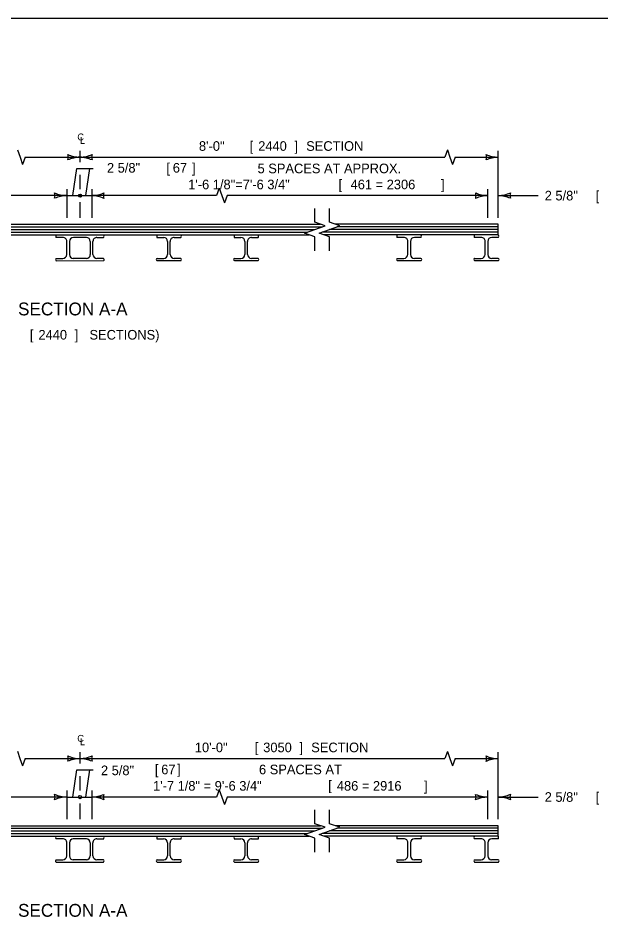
# Model space of a CAD drawing. Extents: x 49991.4 to 50021, y 49987.6 to 50011.4.
# Drawn here: x 50002.38 to 50006.02, y 49993.35 to 49999 of the extents above; entities that cross this region are included whole.
import ezdxf

# ---------------------------------------------------------------- set-up
doc = ezdxf.new("R2010")
doc.units = 0
for name, color, linetype in [('Level 1', 7, 'Continuous'), ('Level 10', 7, 'Continuous'), ('Level 2', 7, 'Continuous'), ('Level 3', 7, 'Continuous'), ('Level 6', 7, 'Continuous')]:
    doc.layers.add(name, color=color, linetype=linetype)

msp = doc.modelspace()

# ---------------------------------------------------------------- linework, layer by layer
at = {"layer": 'Level 1'}
for p, q in [((50001.3411, 49997.7121), (50004.2726, 49997.7121)), ((50005.3818, 49997.7121), (50004.3638, 49997.7121)), ((50005.3818, 49997.6465), (50005.3818, 49997.7121)), ((50001.2596, 49997.663), (50004.1911, 49997.663)), ((50001.2701, 49997.6465), (50004.2016, 49997.6465)), ((50001.3056, 49997.6793), (50004.2371, 49997.6793)), ((50001.3518, 49997.6957), (50004.2833, 49997.6957)), ((50002.6221, 49997.6461), (50002.918, 49997.6462)), ((50003.2526, 49997.646), (50003.4005, 49997.6462)), ((50003.7352, 49997.646), (50003.8832, 49997.6462)), ((50005.3818, 49997.663), (50004.2823, 49997.663)), ((50005.3818, 49997.6465), (50004.2928, 49997.6465)), ((50005.3818, 49997.6793), (50004.3283, 49997.6793)), ((50005.3818, 49997.6957), (50004.3745, 49997.6957)), ((50004.8992, 49997.6461), (50004.7513, 49997.6463)), ((50005.3818, 49997.6461), (50005.2339, 49997.6463)), ((50002.6637, 49997.6297), (50002.6222, 49997.6297)), ((50002.6881, 49997.5237), (50002.6881, 49997.6052)), ((50002.7048, 49997.6051), (50002.7048, 49997.5235)), ((50002.8107, 49997.6297), (50002.7294, 49997.6295)), ((50002.8353, 49997.6052), (50002.8353, 49997.5236)), ((50002.852, 49997.5239), (50002.852, 49997.6053)), ((50002.8763, 49997.6298), (50002.918, 49997.6299)), ((50003.2527, 49997.6296), (50003.2933, 49997.6297)), ((50003.3178, 49997.6052), (50003.3178, 49997.5236)), ((50003.3346, 49997.5239), (50003.3346, 49997.6053)), ((50003.3589, 49997.6298), (50003.4005, 49997.6299)), ((50003.7353, 49997.6296), (50003.7759, 49997.6297)), ((50003.8004, 49997.6052), (50003.8004, 49997.5236)), ((50003.8172, 49997.5239), (50003.8172, 49997.6053)), ((50003.8415, 49997.6298), (50003.8832, 49997.6299)), ((50004.7929, 49997.6299), (50004.7513, 49997.6299)), ((50004.8172, 49997.5239), (50004.8172, 49997.6054)), ((50004.834, 49997.6053), (50004.834, 49997.5237)), ((50004.8992, 49997.6297), (50004.8586, 49997.6298)), ((50005.2755, 49997.6299), (50005.2339, 49997.6299)), ((50005.2998, 49997.5239), (50005.2998, 49997.6054)), ((50005.3166, 49997.6053), (50005.3166, 49997.5237)), ((50005.3818, 49997.6297), (50005.3412, 49997.6298)), ((50002.6213, 49997.4851), (50002.9185, 49997.4852)), ((50002.6221, 49997.4993), (50002.6635, 49997.4993)), ((50002.8108, 49997.4991), (50002.7293, 49997.4989)), ((50002.918, 49997.4994), (50002.8766, 49997.4994)), ((50003.2523, 49997.4852), (50003.4011, 49997.4852)), ((50003.253, 49997.499), (50003.2934, 49997.4991)), ((50003.4006, 49997.4994), (50003.3592, 49997.4994)), ((50003.7348, 49997.4852), (50003.8838, 49997.4852)), ((50003.7356, 49997.499), (50003.776, 49997.4991)), ((50003.8832, 49997.4994), (50003.8418, 49997.4994)), ((50004.7506, 49997.4853), (50004.8999, 49997.4853)), ((50004.7513, 49997.4995), (50004.7927, 49997.4995)), ((50004.8989, 49997.4991), (50004.8584, 49997.4991)), ((50005.233, 49997.4854), (50005.3828, 49997.4854)), ((50005.2339, 49997.4995), (50005.2753, 49997.4995)), ((50005.3815, 49997.4991), (50005.341, 49997.4991)), ((50001.3055, 49993.9253), (50004.237, 49993.9253)), ((50001.341, 49993.9581), (50004.2725, 49993.9581)), ((50001.3517, 49993.9417), (50004.2832, 49993.9417)), ((50005.3817, 49993.9253), (50004.3282, 49993.9253)), ((50005.3817, 49993.9581), (50004.3637, 49993.9581)), ((50005.3817, 49993.9417), (50004.3744, 49993.9417)), ((50005.3817, 49993.8925), (50005.3817, 49993.9581)), ((50001.2595, 49993.909), (50004.191, 49993.909)), ((50001.27, 49993.8925), (50004.2015, 49993.8925)), ((50002.6221, 49993.8921), (50002.9178, 49993.8922)), ((50002.6636, 49993.8757), (50002.6221, 49993.8757)), ((50002.8106, 49993.8757), (50002.7293, 49993.8755)), ((50002.8762, 49993.8758), (50002.9178, 49993.8759)), ((50003.2525, 49993.892), (50003.4005, 49993.8922)), ((50003.2526, 49993.8756), (50003.2932, 49993.8757)), ((50003.3588, 49993.8758), (50003.4005, 49993.8759)), ((50003.7351, 49993.892), (50003.8831, 49993.8922)), ((50003.7352, 49993.8756), (50003.7758, 49993.8757)), ((50003.8414, 49993.8758), (50003.8831, 49993.8759)), ((50005.3817, 49993.909), (50004.2822, 49993.909)), ((50005.3817, 49993.8925), (50004.2927, 49993.8925)), ((50004.8991, 49993.8921), (50004.7512, 49993.8923)), ((50004.7928, 49993.8759), (50004.7512, 49993.8759)), ((50004.8991, 49993.8757), (50004.8585, 49993.8758)), ((50005.3817, 49993.8921), (50005.2338, 49993.8923)), ((50005.2754, 49993.8759), (50005.2338, 49993.8759)), ((50005.3817, 49993.8757), (50005.3411, 49993.8758)), ((50002.688, 49993.7697), (50002.688, 49993.8512)), ((50002.7047, 49993.8511), (50002.7047, 49993.7695)), ((50002.8352, 49993.8512), (50002.8352, 49993.7696)), ((50002.8519, 49993.7699), (50002.8519, 49993.8513)), ((50003.3177, 49993.8512), (50003.3177, 49993.7696)), ((50003.3345, 49993.7699), (50003.3345, 49993.8513)), ((50003.8003, 49993.8512), (50003.8003, 49993.7696)), ((50003.8171, 49993.7699), (50003.8171, 49993.8513)), ((50004.8171, 49993.7699), (50004.8171, 49993.8514)), ((50004.8339, 49993.8513), (50004.8339, 49993.7697)), ((50005.2997, 49993.7699), (50005.2997, 49993.8514)), ((50005.3165, 49993.8513), (50005.3165, 49993.7697)), ((50002.622, 49993.7453), (50002.6634, 49993.7453)), ((50002.8107, 49993.7451), (50002.7292, 49993.7449)), ((50002.9179, 49993.7454), (50002.8765, 49993.7454)), ((50003.2529, 49993.745), (50003.2933, 49993.7451)), ((50003.4005, 49993.7454), (50003.3591, 49993.7454)), ((50003.7355, 49993.745), (50003.7759, 49993.7451)), ((50003.8831, 49993.7454), (50003.8417, 49993.7454)), ((50004.7512, 49993.7455), (50004.7926, 49993.7455)), ((50004.8988, 49993.7451), (50004.8583, 49993.7451)), ((50005.2338, 49993.7455), (50005.2752, 49993.7455)), ((50005.3814, 49993.7451), (50005.3409, 49993.7451)), ((50002.6212, 49993.7311), (50002.9184, 49993.7312)), ((50003.2522, 49993.7312), (50003.401, 49993.7312)), ((50003.7347, 49993.7312), (50003.8837, 49993.7312)), ((50004.7505, 49993.7313), (50004.8998, 49993.7313)), ((50005.2329, 49993.7314), (50005.3827, 49993.7314))]:
    msp.add_line(p, q, dxfattribs=at)
msp.add_lwpolyline([(49999.3835, 49998.9992), (50016.7501, 49998.9992), (50016.7501, 49987.7988), (49999.3835, 49987.7988)], close=True, dxfattribs=at)
for centre, radius, start, end in [((50002.6644, 49997.606), 0.0237, 358.1433, 91.4997), ((50002.7293, 49997.605), 0.0245, 89.8692, 179.8692), ((50002.8108, 49997.6052), 0.0245, 0.1309, 90.1308), ((50002.8756, 49997.6062), 0.0237, 88.3061, 182.0509), ((50003.2933, 49997.6052), 0.0245, 0.1309, 90.1308), ((50003.3572, 49997.6072), 0.0227, 85.6929, 184.6641), ((50003.7759, 49997.6052), 0.0245, 0.1309, 90.1308), ((50003.8406, 49997.6064), 0.0234, 87.6491, 182.7079), ((50004.7943, 49997.6069), 0.023, 356.1633, 93.4797), ((50004.8585, 49997.6053), 0.0245, 89.8692, 179.8692), ((50005.2766, 49997.6066), 0.0233, 356.9743, 92.6686), ((50005.3411, 49997.6053), 0.0245, 89.8692, 179.8692), ((50002.6636, 49997.5238), 0.0245, 269.8691, 359.8691), ((50002.7293, 49997.5234), 0.0245, 179.8691, 269.8691), ((50002.8108, 49997.5236), 0.0245, 270.1309, 0.1308), ((50002.8765, 49997.5239), 0.0245, 180.1309, 270.1309), ((50003.2933, 49997.5236), 0.0245, 270.1309, 0.1308), ((50003.3591, 49997.5239), 0.0245, 180.1309, 270.1309), ((50003.7759, 49997.5236), 0.0245, 270.1309, 0.1308), ((50003.8417, 49997.5239), 0.0245, 180.1309, 270.1309), ((50004.7927, 49997.524), 0.0245, 269.8691, 359.8691), ((50004.8585, 49997.5236), 0.0245, 179.8691, 269.8691), ((50005.2753, 49997.524), 0.0245, 269.8691, 359.8691), ((50005.3411, 49997.5236), 0.0245, 179.8691, 269.8691), ((50002.6661, 49993.8538), 0.022, 353.1725, 96.4705), ((50002.7292, 49993.851), 0.0245, 89.8692, 179.8692), ((50002.8107, 49993.8512), 0.0245, 0.1309, 90.1308), ((50002.8745, 49993.8532), 0.0227, 85.5502, 184.8068), ((50003.2932, 49993.8512), 0.0245, 0.1309, 90.1308), ((50003.3571, 49993.8533), 0.0226, 85.4784, 184.8786), ((50003.7758, 49993.8512), 0.0245, 0.1309, 90.1308), ((50003.8409, 49993.852), 0.0238, 88.6781, 181.6789), ((50004.7953, 49993.8541), 0.022, 353.0206, 96.6224), ((50004.8584, 49993.8513), 0.0245, 89.8692, 179.8692), ((50005.2765, 49993.8527), 0.0233, 356.9044, 92.7386), ((50005.341, 49993.8513), 0.0245, 89.8692, 179.8692), ((50002.6635, 49993.7698), 0.0245, 269.8691, 359.8691), ((50002.7292, 49993.7694), 0.0245, 179.8691, 269.8691), ((50002.8107, 49993.7696), 0.0245, 270.1309, 0.1308), ((50002.8764, 49993.7699), 0.0245, 180.1309, 270.1309), ((50003.2932, 49993.7696), 0.0245, 270.1309, 0.1308), ((50003.359, 49993.7699), 0.0245, 180.1309, 270.1309), ((50003.7758, 49993.7696), 0.0245, 270.1309, 0.1308), ((50003.8416, 49993.7699), 0.0245, 180.1309, 270.1309), ((50004.7926, 49993.77), 0.0245, 269.8691, 359.8691), ((50004.8584, 49993.7696), 0.0245, 179.8691, 269.8691), ((50005.2752, 49993.77), 0.0245, 269.8691, 359.8691), ((50005.341, 49993.7696), 0.0245, 179.8691, 269.8691)]:
    msp.add_arc(centre, radius, start, end, dxfattribs=at)
for centre, major_axis, ratio, start_param, end_param in [((50002.6221, 49997.6379), (-0.00002, 0.00817), 0.356754, 0, 3.141593), ((50002.9179, 49997.638), (0.00002, -0.00817), 0.392805, 0, 3.141593), ((50003.2527, 49997.6378), (-0.00002, 0.00817), 0.356754, 0, 3.141593), ((50003.4005, 49997.638), (0.00002, -0.00817), 0.392805, 0, 3.141593), ((50003.7353, 49997.6378), (-0.00002, 0.00817), 0.356754, 0, 3.141593), ((50003.8831, 49997.638), (0.00002, -0.00817), 0.392805, 0, 3.141593), ((50004.7513, 49997.6381), (-0.00002, -0.00817), 0.392805, 3.141593, 6.283185), ((50004.8992, 49997.6379), (0.00002, 0.00817), 0.356754, 3.141593, 6.283185), ((50005.2339, 49997.6381), (-0.00002, -0.00817), 0.392805, 3.141593, 6.283185), ((50005.3818, 49997.6379), (0.00002, 0.00817), 0.356754, 3.141593, 6.283185), ((50002.6222, 49997.4921), (0.00003, -0.00717), 0.534325, 3.141593, 6.043934), ((50002.9179, 49997.4922), (-0.00003, -0.00717), 0.534325, 0.146109, 3.141593), ((50003.2532, 49997.492), (-0.00025, 0.00695), 0.928868, 0, 2.951883), ((50003.4005, 49997.4922), (-0.00003, -0.00717), 0.534325, 0.161043, 3.141593), ((50003.7358, 49997.492), (-0.00025, 0.00695), 0.928868, 0, 2.93527), ((50003.8831, 49997.4922), (-0.00003, -0.00717), 0.534325, 0.176923, 3.141593), ((50004.7513, 49997.4923), (0.00003, -0.00717), 0.534325, 3.141593, 6.095489), ((50004.8986, 49997.4921), (0.00025, 0.00695), 0.928868, 3.382741, 6.283185), ((50005.2339, 49997.4923), (0.00003, -0.00717), 0.534325, 3.141593, 6.039934), ((50005.3812, 49997.4921), (0.00025, 0.00695), 0.928868, 3.435164, 6.283185), ((50002.6221, 49993.8839), (-0.00002, -0.00817), 0.392805, 3.141593, 6.283185), ((50002.9178, 49993.884), (0.00002, -0.00817), 0.392805, 0, 3.141593), ((50003.2526, 49993.8838), (-0.00002, 0.00817), 0.356754, 0, 3.141593), ((50003.4004, 49993.884), (0.00002, -0.00817), 0.392805, 0, 3.141593), ((50003.7352, 49993.8838), (-0.00002, 0.00817), 0.356754, 0, 3.141593), ((50003.883, 49993.884), (0.00002, -0.00817), 0.392805, 0, 3.141593), ((50004.7512, 49993.8841), (-0.00002, -0.00817), 0.392805, 3.141593, 6.283185), ((50004.8991, 49993.8839), (0.00002, 0.00817), 0.356754, 3.141593, 6.283185), ((50005.2338, 49993.8841), (-0.00002, -0.00817), 0.392805, 3.141593, 6.283185), ((50005.3817, 49993.8839), (0.00002, 0.00817), 0.356754, 3.141593, 6.283185), ((50002.6221, 49993.7381), (0.00003, -0.00717), 0.534325, 3.141593, 6.043934), ((50002.9178, 49993.7382), (-0.00003, -0.00717), 0.534325, 0.146109, 3.141593), ((50003.2531, 49993.738), (-0.00025, 0.00695), 0.928868, 0, 2.951883), ((50003.4004, 49993.7382), (-0.00003, -0.00717), 0.534325, 0.161043, 3.141593), ((50003.7357, 49993.738), (-0.00025, 0.00695), 0.928868, 0, 2.93527), ((50003.883, 49993.7382), (-0.00003, -0.00717), 0.534325, 0.176923, 3.141593), ((50004.7512, 49993.7383), (0.00003, -0.00717), 0.534325, 3.141593, 6.095489), ((50004.8985, 49993.7381), (0.00025, 0.00695), 0.928868, 3.382741, 6.283185), ((50005.2338, 49993.7383), (0.00003, -0.00717), 0.534325, 3.141593, 6.039934), ((50005.3811, 49993.7381), (0.00025, 0.00695), 0.928868, 3.435164, 6.283185)]:
    msp.add_ellipse(centre, major_axis=major_axis, ratio=ratio, start_param=start_param, end_param=end_param, dxfattribs=at)
at = {"layer": 'Level 10'}
msp.add_line((50002.7701, 49994.4169), (50002.7701, 49994.4169), dxfattribs=at)
at = {"layer": 'Level 3'}
for p, q in [((50002.3802, 49998.1765), (50002.3964, 49998.1309)), ((50002.7702, 49998.1709), (50002.7702, 49998.1009)), ((50005.0643, 49998.1762), (50005.0481, 49998.1306)), ((50005.0643, 49998.1762), (50005.0805, 49998.1306)), ((50005.3819, 49997.7521), (50005.3819, 49998.1706)), ((50002.3964, 49998.1309), (50002.4126, 49998.0851)), ((50002.4288, 49998.1309), (50002.4126, 49998.0851)), ((50002.4288, 49998.1309), (50002.7702, 49998.1309)), ((50002.7702, 49998.1309), (50004.5789, 49998.1306)), ((50004.5789, 49998.1306), (50005.0481, 49998.1306)), ((50005.0805, 49998.1306), (50005.0967, 49998.0848)), ((50005.1129, 49998.1306), (50005.0967, 49998.0848)), ((50005.1129, 49998.1306), (50005.3819, 49998.1306)), ((50002.7256, 49997.8912), (50002.7506, 49998.0609)), ((50002.7506, 49998.0609), (50002.8534, 49998.0609)), ((50002.807, 49997.891), (50002.832, 49998.0609)), ((50002.7702, 49998.0209), (50002.7702, 49997.931)), ((50002.6886, 49997.9312), (50002.6886, 49997.7521)), ((50002.8442, 49997.9309), (50002.8442, 49997.7521)), ((50003.6403, 49997.9367), (50003.6241, 49997.8909)), ((50003.6403, 49997.9367), (50003.6565, 49997.8909)), ((50005.3171, 49997.7521), (50005.3171, 49997.9309)), ((50002.6886, 49997.8912), (50001.0764, 49997.8912)), ((50002.6886, 49997.8912), (50002.8442, 49997.8909)), ((50003.6241, 49997.8909), (50002.8442, 49997.8909)), ((50003.6565, 49997.8909), (50003.6727, 49997.8453)), ((50003.6889, 49997.8909), (50003.6727, 49997.8453)), ((50005.3171, 49997.8909), (50003.6889, 49997.8909)), ((50005.3819, 49997.8912), (50005.6321, 49997.8912)), ((50002.7702, 49997.851), (50002.7702, 49997.7521)), ((50002.3801, 49994.4225), (50002.3963, 49994.3769)), ((50005.0642, 49994.4222), (50005.048, 49994.3766)), ((50005.0642, 49994.4222), (50005.0804, 49994.3766)), ((50002.3963, 49994.3769), (50002.4125, 49994.3311)), ((50002.4287, 49994.3769), (50002.4125, 49994.3311)), ((50002.4287, 49994.3769), (50002.7701, 49994.3769)), ((50002.7701, 49994.4169), (50002.7701, 49994.3469)), ((50002.7701, 49994.3769), (50004.5788, 49994.3766)), ((50004.5788, 49994.3766), (50005.048, 49994.3766)), ((50005.0804, 49994.3766), (50005.0966, 49994.3308)), ((50005.1128, 49994.3766), (50005.0966, 49994.3308)), ((50005.1128, 49994.3766), (50005.3818, 49994.3766)), ((50005.3818, 49993.9981), (50005.3818, 49994.4166)), ((50002.7255, 49994.1371), (50002.7505, 49994.3069)), ((50002.7505, 49994.3069), (50002.8533, 49994.3069)), ((50002.7701, 49994.2669), (50002.7701, 49994.177)), ((50002.8069, 49994.137), (50002.8319, 49994.3069)), ((50002.6885, 49994.1772), (50002.6885, 49993.9981)), ((50002.8441, 49994.1769), (50002.8441, 49993.9981)), ((50003.6402, 49994.1827), (50003.624, 49994.1369)), ((50003.6402, 49994.1827), (50003.6564, 49994.1369)), ((50005.317, 49993.9981), (50005.317, 49994.1769)), ((50002.6885, 49994.1372), (50001.0763, 49994.1372)), ((50002.6885, 49994.1372), (50002.8441, 49994.1369)), ((50002.7701, 49994.097), (50002.7701, 49993.9981)), ((50003.624, 49994.1369), (50002.8441, 49994.1369)), ((50003.6564, 49994.1369), (50003.6726, 49994.0913)), ((50003.6888, 49994.1369), (50003.6726, 49994.0913)), ((50005.317, 49994.1369), (50003.6888, 49994.1369)), ((50005.3818, 49994.1372), (50005.632, 49994.1372))]:
    msp.add_line(p, q, dxfattribs=at)
for centre in [(50002.771, 49997.8906), (50002.7709, 49994.1366)]:
    msp.add_circle(centre, 0.01, dxfattribs=at)
for centre, radius, start, end in [((50002.7794, 49998.353), 0.2223, 247.456, 267.6395), ((50002.642, 49998.1309), 0.0548, 342.1388, 17.8612), ((50002.7817, 49997.8982), 0.233, 92.8273, 112.0772), ((50002.7588, 49998.3636), 0.233, 272.8273, 292.0772), ((50002.7611, 49997.9088), 0.2223, 67.456, 87.6395), ((50002.8985, 49998.1309), 0.0548, 162.1388, 197.8612), ((50005.3911, 49998.3528), 0.2223, 247.456, 267.6395), ((50005.2537, 49998.1306), 0.0548, 342.1388, 17.8612), ((50005.3934, 49997.8979), 0.233, 92.8273, 112.0772), ((50002.6978, 49998.1133), 0.2223, 247.456, 267.6395), ((50002.5604, 49997.8912), 0.0548, 342.1388, 17.8612), ((50002.7001, 49997.6585), 0.233, 92.8273, 112.0772), ((50002.8327, 49998.1236), 0.233, 272.8273, 292.0772), ((50002.835, 49997.6688), 0.2223, 67.456, 87.6395), ((50002.9724, 49997.8909), 0.0548, 162.1388, 197.8612), ((50005.3263, 49998.113), 0.2223, 247.456, 267.6395), ((50005.1889, 49997.8909), 0.0548, 342.1388, 17.8612), ((50005.3286, 49997.6582), 0.233, 92.8273, 112.0772), ((50005.3704, 49998.1239), 0.233, 272.8273, 292.0772), ((50005.3727, 49997.6691), 0.2223, 67.456, 87.6395), ((50005.5101, 49997.8912), 0.0548, 162.1388, 197.8612), ((50002.7793, 49994.599), 0.2223, 247.456, 267.6395), ((50002.6419, 49994.3769), 0.0548, 342.1388, 17.8612), ((50002.7816, 49994.1442), 0.233, 92.8273, 112.0772), ((50002.7587, 49994.6096), 0.233, 272.8273, 292.0772), ((50002.761, 49994.1548), 0.2223, 67.456, 87.6395), ((50002.8984, 49994.3769), 0.0548, 162.1388, 197.8612), ((50005.391, 49994.5988), 0.2223, 247.456, 267.6395), ((50005.2536, 49994.3766), 0.0548, 342.1388, 17.8612), ((50005.3933, 49994.1439), 0.233, 92.8273, 112.0772), ((50002.6977, 49994.3593), 0.2223, 247.456, 267.6395), ((50002.5603, 49994.1372), 0.0548, 342.1388, 17.8612), ((50002.8326, 49994.3696), 0.233, 272.8273, 292.0772), ((50002.9723, 49994.1369), 0.0548, 162.1388, 197.8612), ((50005.3262, 49994.359), 0.2223, 247.456, 267.6395), ((50005.1888, 49994.1369), 0.0548, 342.1388, 17.8612), ((50005.3703, 49994.3699), 0.233, 272.8273, 292.0772), ((50005.51, 49994.1372), 0.0548, 162.1388, 197.8612), ((50002.7, 49993.9045), 0.233, 92.8273, 112.0772), ((50002.8349, 49993.9148), 0.2223, 67.456, 87.6395), ((50005.3285, 49993.9042), 0.233, 92.8273, 112.0772), ((50005.3726, 49993.9151), 0.2223, 67.456, 87.6395)]:
    msp.add_arc(centre, radius, start, end, dxfattribs=at)
at = {"layer": 'Level 6'}
for points in [[(50004.2371, 49997.5468), (50004.2371, 49997.6339), (50004.1731, 49997.6566), (50004.3011, 49997.702), (50004.2371, 49997.7247), (50004.2371, 49997.8118)], [(50004.3283, 49997.5468), (50004.3283, 49997.6339), (50004.2643, 49997.6566), (50004.3923, 49997.702), (50004.3283, 49997.7247), (50004.3283, 49997.8118)], [(50004.237, 49993.7928), (50004.237, 49993.8799), (50004.173, 49993.9026), (50004.301, 49993.948), (50004.237, 49993.9707), (50004.237, 49994.0578)], [(50004.3282, 49993.7928), (50004.3282, 49993.8799), (50004.2642, 49993.9026), (50004.3922, 49993.948), (50004.3282, 49993.9707), (50004.3282, 49994.0578)]]:
    msp.add_lwpolyline(points, dxfattribs=at)

# ---------------------------------------------------------------- texts
at = {"layer": 'Level 10'}
for s, p in [('C', (50002.7541, 49998.2356)), ('L', (50002.7705, 49998.2143)), ('C', (50002.754, 49994.4816)), ('L', (50002.7704, 49994.4603))]:
    msp.add_text(s, height=0.0432, dxfattribs=at).set_placement(p)
at = {"layer": 'Level 2'}
for s, height, p in [('8\'-0" ', 0.06, (50003.5135, 49998.1708)), ('[', 0.06, (50003.8303, 49998.1708)), ('2440', 0.06, (50003.8836, 49998.1708)), (']', 0.06, (50004.11, 49998.1708)), (' SECTION', 0.06, (50004.1608, 49998.1708)), ('2 5/8" ', 0.06, (50002.9393, 49998.0347)), ('[', 0.06, (50003.3105, 49998.0347)), (']', 0.06, (50003.4702, 49998.0347)), ('67', 0.06, (50003.3502, 49998.0347)), ('5 SPACES AT APPROX.', 0.06, (50003.8795, 49998.0309)), ('1\'-6 1/8"=7\'-6 3/4" ', 0.06, (50003.4464, 49997.9309)), ('[', 0.06, (50004.385, 49997.9309)), ('461 = 2306', 0.06, (50004.4603, 49997.9309)), (']', 0.06, (50005.0247, 49997.9309)), ('2 5/8" ', 0.06, (50005.6721, 49997.8612)), ('[', 0.06, (50005.9901, 49997.8612)), ('SECTION A-A', 0.08, (50002.3842, 49997.1436)), ('[', 0.06, (50002.4582, 49996.9926)), ('2440', 0.06, (50002.5115, 49996.9926)), (']', 0.06, (50002.7379, 49996.9926)), (' SECTIONS)', 0.06, (50002.8079, 49996.9926)), ('10\'-0" ', 0.06, (50003.4879, 49994.4167)), ('[', 0.06, (50003.8616, 49994.4167)), ('3050', 0.06, (50003.9148, 49994.4167)), (']', 0.06, (50004.1412, 49994.4167)), (' SECTION', 0.06, (50004.1921, 49994.4167)), ('2 5/8" ', 0.06, (50002.9018, 49994.2734)), ('[', 0.06, (50003.2383, 49994.2791)), ('67', 0.06, (50003.278, 49994.2791)), (']', 0.06, (50003.3776, 49994.2816)), ('6 SPACES AT', 0.06, (50003.8884, 49994.2791)), ('1\'-7 1/8" = 9\'-6 3/4" ', 0.06, (50003.2267, 49994.1769)), ('[', 0.06, (50004.3207, 49994.1794)), ('486 = 2916', 0.06, (50004.3745, 49994.1769)), (']', 0.06, (50004.9187, 49994.1769)), ('2 5/8" ', 0.06, (50005.672, 49994.1072)), ('[', 0.06, (50005.99, 49994.1072)), ('SECTION A-A', 0.08, (50002.3841, 49993.3896))]:
    msp.add_text(s, height=height, dxfattribs=at).set_placement(p)

doc.saveas('drawing.dxf')
